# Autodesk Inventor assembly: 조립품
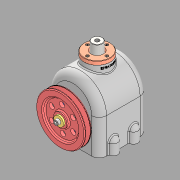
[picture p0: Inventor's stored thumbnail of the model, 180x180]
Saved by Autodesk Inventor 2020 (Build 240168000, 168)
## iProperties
Created: 2023-03
Part Number: 조립품
Document SubType Name: Assembly
Designer: user
Author: user
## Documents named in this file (22)
- C:\Users\user\Desktop\730306V1014\조립품.iam
- C:\Users\user\Desktop\730306V1014\본체.ipt
- C:\Users\user\Desktop\730306V1014\E형 멈춤링 13 x 12.ipt
- C:\Users\user\Desktop\730306V1014\V-벨트풀리.ipt
- C:\Users\user\Desktop\730306V1014\고정핀.ipt
- C:\Users\user\Desktop\730306V1014\뒷커버.ipt
- C:\Users\user\Desktop\730306V1014\링크.ipt
- C:\Users\user\Desktop\730306V1014\멈춤링 25 x 1.2.ipt
- 멈춤링 25 x 1.2.ipt
- C:\Users\user\Desktop\730306V1014\베어링 6205.ipt
- 베어링 6205.ipt
- C:\Users\user\Desktop\730306V1014\볼트 M4 x 12.ipt
- C:\Users\user\Desktop\730306V1014\볼트 M8 x 16.ipt
- C:\Users\user\Desktop\730306V1014\부시.ipt
- C:\Users\user\Desktop\730306V1014\슬라이더.ipt
- C:\Users\user\Desktop\730306V1014\앞커버.ipt
- C:\Users\user\Desktop\730306V1014\엔드캡.ipt
- C:\Users\user\Desktop\730306V1014\오일실 25 40 8.ipt
- 오일실 25 40 8.ipt
- C:\Users\user\Desktop\730306V1014\윗커버.ipt
- C:\Users\user\Desktop\730306V1014\키 6x6x14.ipt
- C:\Users\user\Desktop\730306V1014\편심축.ipt
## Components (3 placed, 3 different names)
1. E형 멈춤링 13 x 12:1
2. V-벨트풀리:1
3. 고정핀:1
